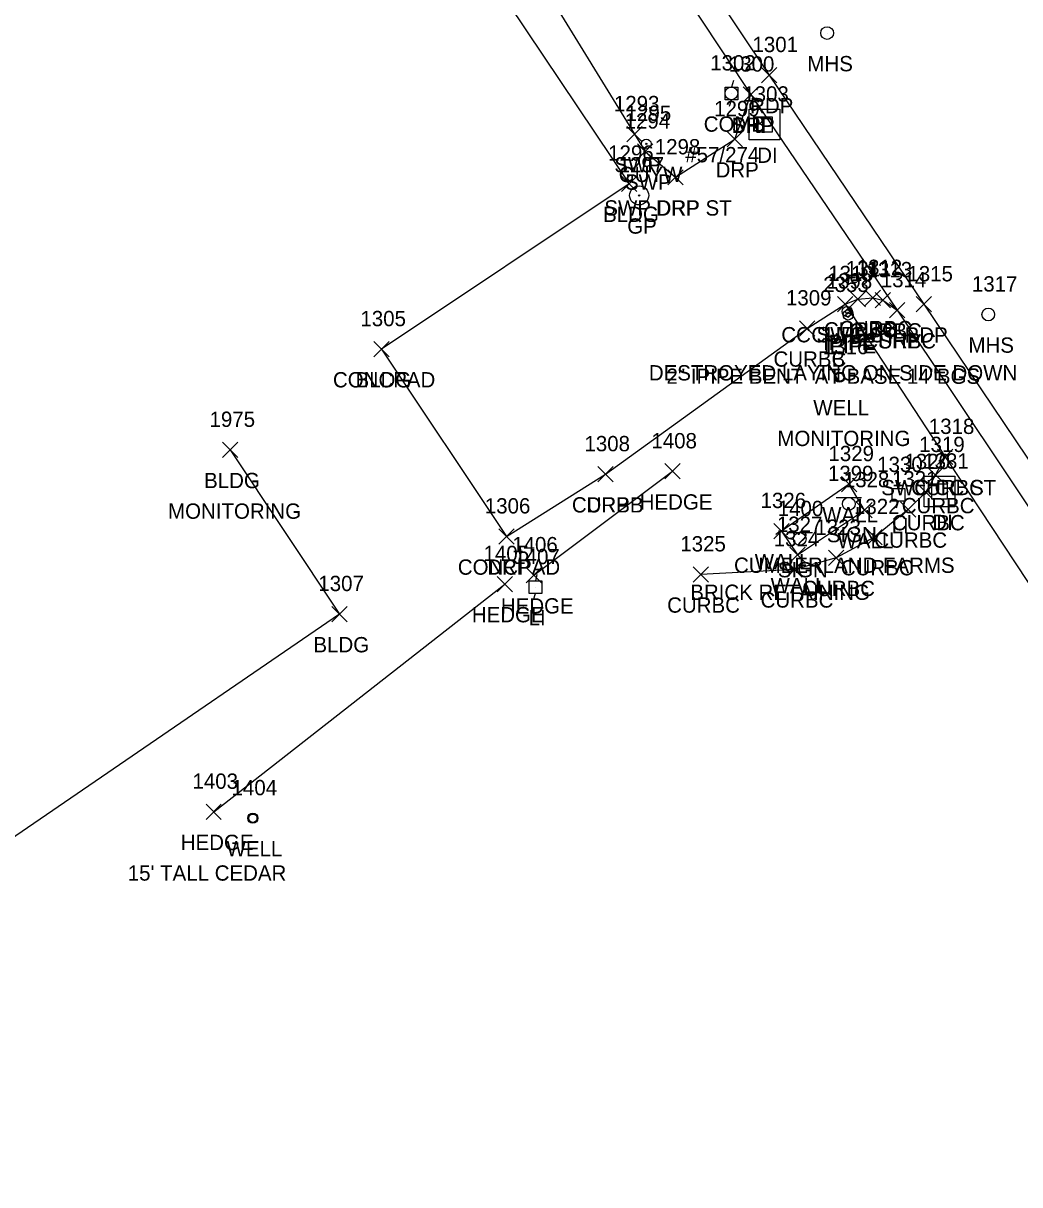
# Model space of a CAD drawing. Extents: x 1635588 to 1637550, y 621583 to 623638.
# Drawn here: x 1636760.5 to 1636890.8, y 622323.2 to 622475 of the extents above; entities that cross this region are included whole.
import ezdxf

# ---------------------------------------------------------------- set-up
doc = ezdxf.new("R2010")
doc.units = 0
for name, color, linetype in [('D_A', 7, 'Continuous'), ('D_I', 7, 'Continuous'), ('DS', 7, 'Continuous'), ('L_A', 7, 'Continuous'), ('L_C', 7, 'Continuous'), ('L_I', 7, 'Continuous'), ('L_TIC', 7, 'Continuous'), ('LAHR', 7, 'Continuous'), ('LBC', 7, 'Continuous'), ('LS', 7, 'Continuous'), ('LW', 7, 'Continuous'), ('M_A', 7, 'Continuous'), ('M_C', 7, 'Continuous'), ('M_I', 7, 'Continuous'), ('MPIP', 7, 'Continuous'), ('P_A', 7, 'Continuous'), ('P_I', 7, 'Continuous'), ('P_TIC', 7, 'Continuous'), ('PET', 7, 'Continuous'), ('PSP', 7, 'Continuous'), ('R_A', 7, 'Continuous'), ('R_I', 7, 'Continuous'), ('R_TIC', 7, 'Continuous'), ('RC', 7, 'Continuous'), ('RDP', 7, 'Continuous'), ('RGP', 7, 'Continuous'), ('RSW', 7, 'Continuous'), ('S_A', 7, 'Continuous'), ('S_C', 7, 'Continuous'), ('S_I', 7, 'Continuous'), ('SSGN', 7, 'Continuous'), ('U_A', 7, 'Continuous'), ('U_C', 7, 'Continuous'), ('U_I', 7, 'Continuous'), ('ULP', 7, 'Continuous'), ('UP', 7, 'Continuous'), ('UPGW', 7, 'Continuous'), ('USMH', 7, 'Continuous'), ('UWW', 7, 'Continuous')]:
    doc.layers.add(name, color=color, linetype=linetype)

msp = doc.modelspace()

# ---------------------------------------------------------------- linework, layer by layer
at = {"layer": 'DS'}
for p, q in [((1636855.42, 622463.74), (1636859.42, 622463.74)), ((1636855.42, 622459.74), (1636855.42, 622463.74)), ((1636856.42, 622460.74), (1636856.42, 622462.74)), ((1636856.42, 622462.74), (1636858.42, 622462.74)), ((1636858.42, 622462.74), (1636858.42, 622460.74)), ((1636859.42, 622463.74), (1636859.42, 622459.74)), ((1636857.43, 622461.74), (1636857.43, 622461.74)), ((1636857.43, 622461.74), (1636857.43, 622461.74)), ((1636859.42, 622459.74), (1636855.42, 622459.74)), ((1636858.42, 622460.74), (1636856.42, 622460.74)), ((1636878.3, 622415.79), (1636882.3, 622415.79)), ((1636878.3, 622411.79), (1636878.3, 622415.79)), ((1636882.3, 622415.79), (1636882.3, 622411.79)), ((1636879.3, 622412.79), (1636879.3, 622414.79)), ((1636879.3, 622414.79), (1636881.3, 622414.79)), ((1636881.3, 622414.79), (1636881.3, 622412.79)), ((1636881.3, 622412.79), (1636879.3, 622412.79)), ((1636880.3, 622413.79), (1636880.3, 622413.79)), ((1636880.3, 622413.79), (1636880.3, 622413.79)), ((1636882.3, 622411.79), (1636878.3, 622411.79))]:
    msp.add_line(p, q, dxfattribs=at)
at = {"layer": 'L_TIC'}
for points in [[(1636838.75, 622453.02), (1636840.75, 622455.02)], [(1636840.75, 622453.02), (1636838.75, 622455.02)], [(1636806.39, 622431.4), (1636808.39, 622433.4)], [(1636808.39, 622431.4), (1636806.39, 622433.4)], [(1636806.39, 622431.4), (1636808.39, 622433.4)], [(1636808.39, 622431.4), (1636806.39, 622433.4)], [(1636786.6, 622418.24), (1636788.6, 622420.24)], [(1636788.6, 622418.24), (1636786.6, 622420.24)], [(1636844.42, 622415.44), (1636846.42, 622417.44)], [(1636846.42, 622415.44), (1636844.42, 622417.44)], [(1636867.49, 622413.77), (1636869.49, 622415.77)], [(1636869.49, 622413.77), (1636867.49, 622415.77)], [(1636869.49, 622410.36), (1636871.49, 622412.36)], [(1636871.49, 622410.36), (1636869.49, 622412.36)], [(1636858.66, 622407.64), (1636860.66, 622409.64)], [(1636860.66, 622407.64), (1636858.66, 622409.64)], [(1636822.7, 622406.93), (1636824.7, 622408.93)], [(1636824.7, 622406.93), (1636822.7, 622408.93)], [(1636860.74, 622404.52), (1636862.74, 622406.52)], [(1636862.74, 622404.52), (1636860.74, 622406.52)], [(1636826.28, 622401.86), (1636828.28, 622403.86)], [(1636828.28, 622401.86), (1636826.28, 622403.86)], [(1636822.48, 622400.71), (1636824.48, 622402.71)], [(1636824.48, 622400.71), (1636822.48, 622402.71)], [(1636800.89, 622396.79), (1636802.89, 622398.79)], [(1636802.89, 622396.79), (1636800.89, 622398.79)], [(1636784.44, 622370.96), (1636786.44, 622372.96)], [(1636786.44, 622370.96), (1636784.44, 622372.96)]]:
    msp.add_lwpolyline(points, dxfattribs=at)
at = {"layer": 'LAHR'}
for points in [[(1636827.28, 622402.86), (1636845.42, 622416.44)], [(1636785.44, 622371.96), (1636823.48, 622401.71)]]:
    msp.add_lwpolyline(points, dxfattribs=at)
at = {"layer": 'LBC'}
for points in [[(1636762.84, 622569.3), (1636812.75, 622494.27), (1636839.75, 622454.02), (1636807.39, 622432.4)], [(1636787.6, 622419.24), (1636801.89, 622397.79)], [(1636801.89, 622397.79), (1636737.96, 622354.06)]]:
    msp.add_lwpolyline(points, dxfattribs=at)
at = {"layer": 'LS'}
msp.add_lwpolyline([(1636807.39, 622432.4), (1636823.7, 622407.93)], dxfattribs=at)
at = {"layer": 'LW'}
msp.add_lwpolyline([(1636859.66, 622408.64), (1636861.74, 622405.52), (1636870.49, 622411.36), (1636868.49, 622414.77), (1636859.66, 622408.64)], dxfattribs=at)
at = {"layer": 'MPIP'}
for points in [[(1636868.59, 622437.31), (1636868.25, 622437.64), (1636867.92, 622437.31), (1636868.25, 622436.97)], [(1636868.7, 622436.87), (1636868.37, 622437.2), (1636868.03, 622436.87), (1636868.37, 622436.53)]]:
    msp.add_lwpolyline(points, close=True, dxfattribs=at)
for centre in [(1636868.25, 622437.31), (1636868.37, 622436.87)]:
    msp.add_circle(centre, 0.667, dxfattribs=at)
at = {"layer": 'P_TIC'}
for points in [[(1636857.06, 622467.21), (1636859.06, 622469.21)], [(1636859.06, 622467.21), (1636857.06, 622469.21)], [(1636854.63, 622464.66), (1636856.63, 622466.66)], [(1636856.63, 622464.66), (1636854.63, 622466.66)], [(1636873.76, 622436.49), (1636875.76, 622438.49)], [(1636875.76, 622436.49), (1636873.76, 622438.49)], [(1636877.24, 622437.26), (1636879.24, 622439.26)], [(1636879.24, 622437.26), (1636877.24, 622439.26)]]:
    msp.add_lwpolyline(points, dxfattribs=at)
at = {"layer": 'PET'}
msp.add_lwpolyline([(1636496.54, 623045.3), (1636533.69, 622970.65), (1636546.95, 622944.69), (1636557.06, 622926.23), (1636579, 622887.89), (1636603.72, 622849.48), (1636616.07, 622830.82), (1636647.79, 622783.76), (1636703.25, 622700.68), (1636737.08, 622649.81), (1636763.83, 622609.67), (1636812.95, 622535.62), (1636858.06, 622468.21), (1636878.24, 622438.26), (1636911.18, 622389.38), (1636974.88, 622293.33), (1636986.61, 622276.7), (1637016.63, 622231.99)], dxfattribs=at)
at = {"layer": 'PSP'}
msp.add_lwpolyline([(1636412.61, 623220.07), (1636436.6, 623167.3), (1636456.23, 623125.07), (1636460.67, 623115.98), (1636475.52, 623084.87), (1636494.51, 623045.42), (1636524.16, 622986.51), (1636530.74, 622972.24), (1636554.07, 622925.3), (1636577.18, 622886.3), (1636601.72, 622847.41), (1636613.46, 622830.09), (1636645.38, 622782.47), (1636700.61, 622698.86), (1636734.28, 622648.07), (1636752.12, 622619.3), (1636752.46, 622616.81), (1636755.34, 622613.42), (1636810.04, 622534.39), (1636855.63, 622465.66), (1636874.76, 622437.49), (1636904.15, 622393.55)], dxfattribs=at)
at = {"layer": 'R_TIC'}
for points in [[(1636854.63, 622464.66), (1636856.63, 622466.66)], [(1636856.63, 622464.66), (1636854.63, 622466.66)], [(1636839.44, 622459.49), (1636841.44, 622461.49)], [(1636841.44, 622459.49), (1636839.44, 622461.49)], [(1636852.55, 622458.83), (1636854.55, 622460.83)], [(1636854.55, 622458.83), (1636852.55, 622460.83)], [(1636840.84, 622457.22), (1636842.84, 622459.22)], [(1636842.84, 622457.22), (1636840.84, 622459.22)], [(1636844.78, 622453.85), (1636846.78, 622455.85)], [(1636846.78, 622453.85), (1636844.78, 622455.85)], [(1636844.78, 622453.85), (1636846.78, 622455.85)], [(1636846.78, 622453.85), (1636844.78, 622455.85)], [(1636870.6, 622438.09), (1636872.6, 622440.09)], [(1636872.6, 622438.09), (1636870.6, 622440.09)], [(1636866.97, 622437.29), (1636868.97, 622439.29)], [(1636868.97, 622437.29), (1636866.97, 622439.29)], [(1636866.97, 622437.29), (1636868.97, 622439.29)], [(1636868.97, 622437.29), (1636866.97, 622439.29)], [(1636868.62, 622437.92), (1636870.62, 622439.92)], [(1636870.62, 622437.92), (1636868.62, 622439.92)], [(1636871.9, 622437.79), (1636873.9, 622439.79)], [(1636873.9, 622437.79), (1636871.9, 622439.79)], [(1636873.76, 622436.49), (1636875.76, 622438.49)], [(1636875.76, 622436.49), (1636873.76, 622438.49)], [(1636862.02, 622434.11), (1636864.02, 622436.11)], [(1636864.02, 622434.11), (1636862.02, 622436.11)], [(1636862.02, 622434.11), (1636864.02, 622436.11)], [(1636864.02, 622434.11), (1636862.02, 622436.11)], [(1636880.03, 622417.32), (1636882.03, 622419.32)], [(1636882.03, 622417.32), (1636880.03, 622419.32)], [(1636880.03, 622417.32), (1636882.03, 622419.32)], [(1636882.03, 622417.32), (1636880.03, 622419.32)], [(1636835.67, 622415.06), (1636837.67, 622417.06)], [(1636837.67, 622415.06), (1636835.67, 622417.06)], [(1636835.67, 622415.06), (1636837.67, 622417.06)], [(1636837.67, 622415.06), (1636835.67, 622417.06)], [(1636878.78, 622414.96), (1636880.78, 622416.96)], [(1636880.78, 622414.96), (1636878.78, 622416.96)], [(1636877.5, 622412.73), (1636879.5, 622414.73)], [(1636879.5, 622412.73), (1636877.5, 622414.73)], [(1636875.21, 622410.46), (1636877.21, 622412.46)], [(1636877.21, 622410.46), (1636875.21, 622412.46)], [(1636822.7, 622406.93), (1636824.7, 622408.93)], [(1636824.7, 622406.93), (1636822.7, 622408.93)], [(1636870.83, 622406.85), (1636872.83, 622408.85)], [(1636872.83, 622406.85), (1636870.83, 622408.85)], [(1636865.78, 622404.14), (1636867.78, 622406.14)], [(1636867.78, 622404.14), (1636865.78, 622406.14)], [(1636848.13, 622401.97), (1636850.13, 622403.97)], [(1636850.13, 622401.97), (1636848.13, 622403.97)], [(1636860.34, 622402.63), (1636862.34, 622404.63)], [(1636862.34, 622402.63), (1636860.34, 622404.63)]]:
    msp.add_lwpolyline(points, dxfattribs=at)
at = {"layer": 'RC'}
for points in [[(1636863.02, 622435.11), (1636867.97, 622438.29), (1636869.62, 622438.92), (1636871.6, 622439.09), (1636872.9, 622438.79), (1636874.76, 622437.49)], [(1636836.67, 622416.06), (1636863.02, 622435.11)], [(1636881.03, 622418.32), (1636879.78, 622415.96), (1636878.5, 622413.73), (1636876.21, 622411.46), (1636871.83, 622407.85), (1636866.78, 622405.14), (1636861.34, 622403.63), (1636849.13, 622402.97)]]:
    msp.add_lwpolyline(points, dxfattribs=at)
at = {"layer": 'RDP'}
for points in [[(1636845.78, 622454.85), (1636853.55, 622459.83), (1636855.63, 622465.66)], [(1636823.7, 622407.93), (1636836.67, 622416.06)]]:
    msp.add_lwpolyline(points, dxfattribs=at)
at = {"layer": 'RGP'}
msp.add_line((1636841.05, 622452.49), (1636841.05, 622452.49), dxfattribs=at)
for radius in [1.25, 0.0833]:
    msp.add_circle((1636841.05, 622452.49), radius, dxfattribs=at)
at = {"layer": 'RSW'}
for points in [[(1636812.75, 622494.27), (1636818.23, 622496.63), (1636840.44, 622460.49), (1636841.84, 622458.22), (1636845.78, 622454.85)], [(1636867.97, 622438.29), (1636881.03, 622418.32), (1636899.45, 622390.51), (1636913.49, 622369.76), (1636944.08, 622324.04), (1636964.21, 622293.73), (1636967.42, 622288.84), (1636978.75, 622271.94)]]:
    msp.add_lwpolyline(points, dxfattribs=at)
at = {"layer": 'SSGN'}
for p, q in [((1636866.8, 622413.03), (1636870.13, 622413.03)), ((1636868.45, 622412.19), (1636868.45, 622412.19)), ((1636860.39, 622408.45), (1636863.72, 622408.45)), ((1636862.04, 622407.61), (1636862.04, 622407.61))]:
    msp.add_line(p, q, dxfattribs=at)
for centre in [(1636868.45, 622412.19), (1636862.04, 622407.61)]:
    msp.add_circle(centre, 0.833, dxfattribs=at)
at = {"layer": 'ULP'}
for p, q in [((1636874.11, 622412.52), (1636874.11, 622414.19)), ((1636874.11, 622414.19), (1636875.78, 622414.19)), ((1636875.11, 622415.02), (1636874.94, 622414.19)), ((1636875.78, 622414.19), (1636875.78, 622412.52)), ((1636874.94, 622413.35), (1636874.94, 622413.35)), ((1636875.78, 622412.52), (1636874.11, 622412.52)), ((1636874.69, 622411.69), (1636874.94, 622412.52)), ((1636826.67, 622400.47), (1636826.67, 622402.14)), ((1636826.67, 622402.14), (1636828.33, 622402.14)), ((1636827.67, 622402.97), (1636827.5, 622402.14)), ((1636828.33, 622402.14), (1636828.33, 622400.47)), ((1636828.33, 622400.47), (1636826.67, 622400.47)), ((1636827.25, 622399.64), (1636827.5, 622400.47)), ((1636827.5, 622401.31), (1636827.5, 622401.31))]:
    msp.add_line(p, q, dxfattribs=at)
at = {"layer": 'UP'}
for p, q in [((1636853.36, 622467.48), (1636853.11, 622466.65)), ((1636852.27, 622464.98), (1636852.27, 622466.65)), ((1636852.27, 622466.65), (1636853.94, 622466.65)), ((1636853.11, 622465.81), (1636853.11, 622465.81)), ((1636853.94, 622466.65), (1636853.94, 622464.98)), ((1636853.94, 622464.98), (1636852.27, 622464.98)), ((1636852.86, 622464.15), (1636853.11, 622464.98))]:
    msp.add_line(p, q, dxfattribs=at)
msp.add_circle((1636853.11, 622465.81), 0.833, dxfattribs=at)
at = {"layer": 'UPGW'}
for radius in [0.625, 0.0833]:
    msp.add_circle((1636841.98, 622459.23), radius, dxfattribs=at)
at = {"layer": 'USMH'}
for p, q in [((1636865.62, 622473.7), (1636865.62, 622473.7)), ((1636866.45, 622473.7), (1636866.45, 622473.7)), ((1636886.67, 622436.93), (1636886.67, 622436.93)), ((1636887.5, 622436.93), (1636887.5, 622436.93))]:
    msp.add_line(p, q, dxfattribs=at)
for centre in [(1636865.62, 622473.7), (1636886.67, 622436.93)]:
    msp.add_circle(centre, 0.833, dxfattribs=at)
at = {"layer": 'UWW'}
for centre, radius in [((1636867.24, 622428.74), 0.667), ((1636867.24, 622428.74), 0.625), ((1636867.24, 622428.74), 0.583), ((1636867.24, 622428.74), 0.542), ((1636790.56, 622371.12), 0.667), ((1636790.56, 622371.12), 0.625), ((1636790.56, 622371.12), 0.583), ((1636790.56, 622371.12), 0.542)]:
    msp.add_circle(centre, radius, dxfattribs=at)

# ---------------------------------------------------------------- texts
at = {"layer": 'D_A'}
for p in [(1636856.48, 622456.74), (1636879.36, 622408.79)]:
    msp.add_text('DI', height=2, dxfattribs=at).set_placement(p)
at = {"layer": 'D_I'}
for s, p in [('1303', (1636854.66, 622464.74)), ('1331', (1636878.18, 622416.79))]:
    msp.add_text(s, height=2, dxfattribs=at).set_placement(p)
at = {"layer": 'L_A'}
for s, p in [('BLDG', (1636836.34, 622449.02)), ('CONCPAD', (1636801.03, 622427.4)), ('BLDG', (1636803.98, 622427.4)), ('BLDG', (1636784.19, 622414.24)), ('HEDGE', (1636841.12, 622411.44)), ('WALL', (1636864.97, 622409.77)), ('WALL', (1636866.98, 622406.36)), ('WALL', (1636856.15, 622403.64)), ('CONCPAD', (1636817.35, 622402.93)), ('WALL', (1636858.23, 622400.52)), ('HEDGE', (1636822.98, 622397.86)), ('HEDGE', (1636819.18, 622396.71)), ('BLDG', (1636798.48, 622392.79)), ('HEDGE', (1636781.14, 622366.96))]:
    msp.add_text(s, height=2, dxfattribs=at).set_placement(p)
at = {"layer": 'L_C'}
for s, p in [('MONITORING', (1636779.48, 622410.24)), ('BRICK RETAINING', (1636847.73, 622399.64)), ("15' TALL CEDAR", (1636774.21, 622362.96))]:
    msp.add_text(s, height=2, dxfattribs=at).set_placement(p)
at = {"layer": 'L_I'}
for s, p in [('1296', (1636837, 622457.02)), ('1305', (1636804.62, 622435.4)), ('1305', (1636804.62, 622435.4)), ('1975', (1636784.9, 622422.24)), ('1408', (1636842.65, 622419.44)), ('1329', (1636865.79, 622417.77)), ('1328', (1636867.8, 622414.36)), ('1306', (1636820.88, 622410.93)), ('1326', (1636856.92, 622411.64)), ('1327', (1636859.05, 622408.52)), ('1405', (1636820.71, 622404.71)), ('1406', (1636824.46, 622405.86)), ('1307', (1636799.12, 622400.79)), ('1403', (1636782.67, 622374.96))]:
    msp.add_text(s, height=2, dxfattribs=at).set_placement(p)
at = {"layer": 'M_A'}
for p in [(1636865.09, 622432.31), (1636865.2, 622431.87)]:
    msp.add_text('IPIPE', height=2, dxfattribs=at).set_placement(p)
at = {"layer": 'M_C'}
for s, p in [('DESTROYED LAYING ON SIDE DOWN', (1636842.32, 622428.31)), ('2" IPIPE BENT  AT BASE 14"BGS', (1636844.62, 622427.87))]:
    msp.add_text(s, height=2, dxfattribs=at).set_placement(p)
at = {"layer": 'M_I'}
for s, p in [('2353', (1636865.11, 622439.87)), ('1398', (1636865.56, 622440.31))]:
    msp.add_text(s, height=2, dxfattribs=at).set_placement(p)
at = {"layer": 'P_A'}
for s, p in [('RDP', (1636855.55, 622463.21)), ('SHP', (1636853.17, 622460.66)), ('SHP', (1636872.29, 622432.49)), ('RDP', (1636875.73, 622433.26))]:
    msp.add_text(s, height=2, dxfattribs=at).set_placement(p)
at = {"layer": 'P_I'}
for s, p in [('1301', (1636855.86, 622471.21)), ('1300', (1636852.77, 622468.66)), ('1315', (1636876.11, 622441.26)), ('1314', (1636872.63, 622440.49))]:
    msp.add_text(s, height=2, dxfattribs=at).set_placement(p)
at = {"layer": 'R_A'}
for s, p in [('DRP', (1636853.12, 622460.66)), ('SWP', (1636837.81, 622455.49)), ('DRP', (1636851.04, 622454.83)), ('SWP', (1636839.2, 622453.22)), ('SWP DRP ST', (1636836.5, 622449.85)), ('DRP', (1636843.27, 622449.85)), ('GP', (1636839.49, 622447.49)), ('CURBC', (1636865.2, 622433.92)), ('CURBC', (1636867.19, 622434.09)), ('CURBC', (1636868.49, 622433.79)), ('CC SWC ST', (1636859.63, 622433.29)), ('CURBC', (1636863.55, 622433.29)), ('CURBC', (1636870.34, 622432.49)), ('CURBB', (1636858.61, 622430.11)), ('CURBC', (1636858.61, 622430.11)), ('SWC CC ST', (1636872.69, 622413.32)), ('CURBC', (1636876.61, 622413.32)), ('CURBB', (1636832.26, 622411.06)), ('DRP', (1636834.16, 622411.06)), ('CURBC', (1636875.37, 622410.96)), ('CURBC', (1636874.09, 622408.73)), ('CURBC', (1636871.79, 622406.46)), ('DRP', (1636821.19, 622402.93)), ('CURBC', (1636867.41, 622402.85)), ('CURBC', (1636862.36, 622400.14)), ('CURBC', (1636856.92, 622398.63)), ('CURBC', (1636844.71, 622397.97))]:
    msp.add_text(s, height=2, dxfattribs=at).set_placement(p)
at = {"layer": 'R_I'}
for s, p in [('1300', (1636852.77, 622468.66)), ('1293', (1636837.75, 622463.49)), ('1299', (1636850.85, 622462.83)), ('1294', (1636839.15, 622461.22)), ('1298', (1636843.09, 622457.85)), ('1298', (1636843.09, 622457.85)), ('1297', (1636838.36, 622455.49)), ('1310', (1636865.76, 622441.29)), ('1310', (1636865.76, 622441.29)), ('1311', (1636868.06, 622441.92)), ('1312', (1636869.48, 622442.09)), ('1313', (1636870.78, 622441.79)), ('1314', (1636872.63, 622440.49)), ('1309', (1636860.24, 622438.11)), ('1309', (1636860.24, 622438.11)), ('1318', (1636878.91, 622421.32)), ('1318', (1636878.91, 622421.32)), ('1308', (1636833.9, 622419.06)), ('1308', (1636833.9, 622419.06)), ('1319', (1636877.65, 622418.96)), ('1320', (1636875.72, 622416.73)), ('1321', (1636874.09, 622414.46)), ('1306', (1636820.88, 622410.93)), ('1322', (1636869.13, 622410.85)), ('1323', (1636864.08, 622408.14)), ('1324', (1636858.64, 622406.63)), ('1325', (1636846.43, 622405.97))]:
    msp.add_text(s, height=2, dxfattribs=at).set_placement(p)
at = {"layer": 'S_A'}
for p in [(1636865.58, 622407.17), (1636859.17, 622402.59)]:
    msp.add_text('SIGN', height=2, dxfattribs=at).set_placement(p)
at = {"layer": 'S_C'}
msp.add_text('CUMBERLAND FARMS', height=2, dxfattribs=at).set_placement((1636853.45, 622403.17))
at = {"layer": 'S_I'}
for s, p in [('1399', (1636865.73, 622415.17)), ('1400', (1636859.16, 622410.59))]:
    msp.add_text(s, height=2, dxfattribs=at).set_placement(p)
at = {"layer": 'U_A'}
for s, p in [('MHS', (1636863.04, 622468.7)), ('COMB', (1636849.49, 622460.81)), ('GUYW', (1636838.38, 622454.23)), ('MHS', (1636884.09, 622431.93)), ('WELL', (1636863.81, 622423.74)), ('LI', (1636874.05, 622408.35)), ('LI', (1636826.6, 622396.31)), ('WELL', (1636787.12, 622366.12))]:
    msp.add_text(s, height=2, dxfattribs=at).set_placement(p)
at = {"layer": 'U_C'}
for s, p in [('#57/274', (1636847.08, 622456.81)), ('MONITORING', (1636859.12, 622419.74))]:
    msp.add_text(s, height=2, dxfattribs=at).set_placement(p)
at = {"layer": 'U_I'}
for s, p in [('1302', (1636850.34, 622468.81)), ('1295', (1636839.29, 622462.23)), ('1317', (1636884.54, 622439.93)), ('1316', (1636865.06, 622431.74)), ('1330', (1636872.16, 622416.35)), ('1407', (1636824.73, 622404.31)), ('1404', (1636787.78, 622374.12))]:
    msp.add_text(s, height=2, dxfattribs=at).set_placement(p)

doc.saveas('drawing.dxf')
